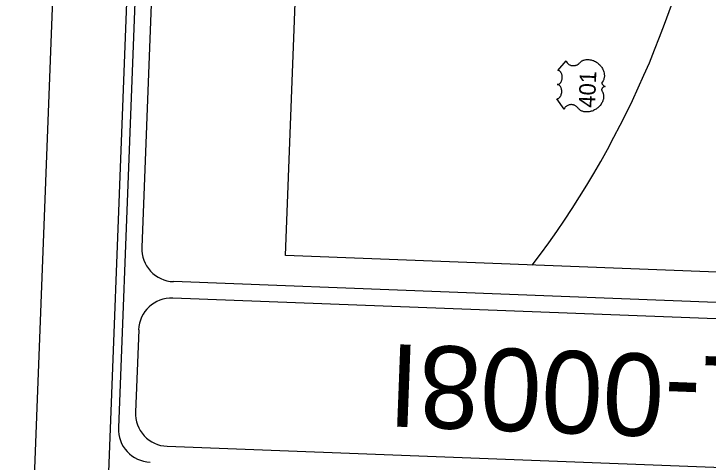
# Model space of a CAD drawing. Extents: x 2094564 to 2100382, y 679033 to 692366.
# Drawn here: x 2094564 to 2095618, y 683117 to 683797 of the extents above; entities that cross this region are included whole.
import ezdxf

# ---------------------------------------------------------------- set-up
doc = ezdxf.new("R2010")
doc.units = 0
for name, color, linetype in [('Default', 7, 'Continuous'), ('Pattern 17', 7, 'Continuous'), ('Prop Horizontal Alignment Direction Label', 7, 'Continuous'), ('Prop Horizontal Alignment Tick Label', 7, 'Continuous'), ('Prop Horizontal Alignment Tick Large', 7, 'Continuous')]:
    doc.layers.add(name, color=color, linetype=linetype)

msp = doc.modelspace()

# ---------------------------------------------------------------- linework, layer by layer
at = {"layer": 'Default'}
for p, q in [((2095431.1, 683727.5), (2095432.6, 683727.8)), ((2095432.6, 683727.8), (2095433.3, 683727.8)), ((2095433.3, 683727.8), (2095434.8, 683727.9)), ((2095434.8, 683727.9), (2095436.5, 683727.8)), ((2095436.5, 683727.8), (2095438.2, 683727.6)), ((2095389.4, 683711.4), (2095402, 683726)), ((2095402, 683726), (2095402.1, 683725.6)), ((2095402.1, 683725.6), (2095402.5, 683724.8)), ((2095402.5, 683724.8), (2095402.9, 683724.1)), ((2095402.9, 683724.1), (2095403.6, 683723)), ((2095403.6, 683723), (2095403.9, 683722.6)), ((2095403.9, 683722.6), (2095404.3, 683722.1)), ((2095404.3, 683722.1), (2095404.8, 683721.7)), ((2095404.8, 683721.7), (2095405.2, 683721.3)), ((2095405.2, 683721.3), (2095405.8, 683720.9)), ((2095405.8, 683720.9), (2095406.3, 683720.4)), ((2095406.3, 683720.4), (2095407, 683720)), ((2095407, 683720), (2095407.6, 683719.7)), ((2095407.6, 683719.7), (2095408.8, 683719.2)), ((2095408.8, 683719.2), (2095409.5, 683719)), ((2095409.5, 683719), (2095410.2, 683718.8)), ((2095410.2, 683718.8), (2095411.5, 683718.6)), ((2095411.5, 683718.6), (2095412.1, 683718.5)), ((2095412.1, 683718.5), (2095412.8, 683718.5)), ((2095412.8, 683718.5), (2095413.4, 683718.5)), ((2095413.4, 683718.5), (2095414.1, 683718.5)), ((2095414.1, 683718.5), (2095414.8, 683718.6)), ((2095414.8, 683718.6), (2095415.3, 683718.7)), ((2095415.3, 683718.7), (2095416.1, 683718.9)), ((2095416.1, 683718.9), (2095416.9, 683719.1)), ((2095416.9, 683719.1), (2095417.7, 683719.4)), ((2095417.7, 683719.4), (2095419.1, 683720)), ((2095419.1, 683720), (2095420.4, 683720.9)), ((2095420.4, 683720.9), (2095421.2, 683721.5)), ((2095421.2, 683721.5), (2095421.9, 683722.1)), ((2095421.9, 683722.1), (2095422.7, 683723)), ((2095422.7, 683723), (2095423.2, 683723.5)), ((2095423.2, 683723.5), (2095423.8, 683724)), ((2095423.8, 683724), (2095424.9, 683724.9)), ((2095424.9, 683724.9), (2095425.4, 683725.3)), ((2095425.4, 683725.3), (2095426, 683725.6)), ((2095426, 683725.6), (2095426.6, 683726)), ((2095426.6, 683726), (2095427.3, 683726.3)), ((2095427.3, 683726.3), (2095427.9, 683726.6)), ((2095427.9, 683726.6), (2095429.2, 683727)), ((2095429.2, 683727), (2095430.4, 683727.4)), ((2095430.4, 683727.4), (2095431.1, 683727.5)), ((2095438.2, 683727.6), (2095440.1, 683727.3)), ((2095440.1, 683727.3), (2095441.2, 683727)), ((2095441.2, 683727), (2095442.6, 683726.5)), ((2095442.6, 683726.5), (2095443.7, 683726.1)), ((2095443.7, 683726.1), (2095445.4, 683725.3)), ((2095445.4, 683725.3), (2095446.6, 683724.7)), ((2095446.6, 683724.7), (2095448, 683723.8)), ((2095448, 683723.8), (2095448.9, 683723.2)), ((2095448.9, 683723.2), (2095449.8, 683722.6)), ((2095449.8, 683722.6), (2095450.9, 683721.7)), ((2095450.9, 683721.7), (2095452, 683720.8)), ((2095452, 683720.8), (2095453.2, 683719.6)), ((2095453.2, 683719.6), (2095454, 683718.7)), ((2095454, 683718.7), (2095455, 683717.5)), ((2095455, 683717.5), (2095455.6, 683716.7)), ((2095389.9, 683711.3), (2095389.4, 683711.4)), ((2095390.4, 683711.2), (2095389.9, 683711.3)), ((2095391, 683711.1), (2095390.4, 683711.2)), ((2095391.6, 683710.8), (2095391, 683711.1)), ((2095392.1, 683710.5), (2095391.6, 683710.8)), ((2095392.6, 683710.1), (2095392.1, 683710.5)), ((2095393.3, 683709.5), (2095392.6, 683710.1)), ((2095393.9, 683708.8), (2095393.3, 683709.5)), ((2095394.3, 683708.2), (2095393.9, 683708.8)), ((2095394.8, 683707.5), (2095394.3, 683708.2)), ((2095395.2, 683706.5), (2095394.8, 683707.5)), ((2095455.6, 683716.7), (2095456.3, 683715.7)), ((2095456.3, 683715.7), (2095457.2, 683714.3)), ((2095457.2, 683714.3), (2095457.9, 683712.9)), ((2095457.9, 683712.9), (2095458.5, 683711.7)), ((2095458.5, 683711.7), (2095458.9, 683710.6)), ((2095458.9, 683710.6), (2095459.4, 683709.3)), ((2095459.4, 683709.3), (2095459.9, 683707)), ((2095459.9, 683707), (2095460, 683706.2)), ((2095395.5, 683705.8), (2095395.2, 683706.5)), ((2095395.3, 683695.5), (2095395.6, 683696.3)), ((2095395.8, 683705), (2095395.5, 683705.8)), ((2095395.6, 683696.3), (2095395.8, 683697.1)), ((2095396, 683704), (2095395.8, 683705)), ((2095395.8, 683697.1), (2095396, 683697.9)), ((2095396.1, 683703.3), (2095396, 683704)), ((2095396, 683697.9), (2095396.1, 683698.7)), ((2095396.2, 683702.5), (2095396.1, 683703.3)), ((2095396.1, 683698.7), (2095396.2, 683699.5)), ((2095396.3, 683701.7), (2095396.2, 683702.5)), ((2095396.2, 683700.1), (2095396.3, 683701)), ((2095396.2, 683699.5), (2095396.2, 683700.1)), ((2095396.3, 683701), (2095396.3, 683701.7)), ((2095458.7, 683696.6), (2095458.1, 683695.6)), ((2095459.1, 683697.7), (2095458.7, 683696.6)), ((2095459.5, 683698.9), (2095459.1, 683697.7)), ((2095459.8, 683700), (2095459.5, 683698.9)), ((2095460, 683701.1), (2095459.8, 683700)), ((2095460, 683706.2), (2095460.1, 683705.2)), ((2095460.2, 683702.3), (2095460, 683701.1)), ((2095460.1, 683705.2), (2095460.2, 683704.3)), ((2095460.2, 683704.3), (2095460.2, 683703.5)), ((2095460.2, 683703.5), (2095460.2, 683702.3)), ((2095389.5, 683689.7), (2095388.6, 683689.8)), ((2095388.6, 683689.8), (2095389.3, 683689.8)), ((2095389.3, 683689.8), (2095389.8, 683689.9)), ((2095389.9, 683689.6), (2095389.5, 683689.7)), ((2095389.8, 683689.9), (2095390.2, 683690)), ((2095390.8, 683689.3), (2095389.9, 683689.6)), ((2095390.2, 683690), (2095390.7, 683690.2)), ((2095390.7, 683690.2), (2095391.3, 683690.4)), ((2095391.2, 683689), (2095390.8, 683689.3)), ((2095391.6, 683688.7), (2095391.2, 683689)), ((2095391.3, 683690.4), (2095391.9, 683690.8)), ((2095392.4, 683688.1), (2095391.6, 683688.7)), ((2095391.9, 683690.8), (2095392.7, 683691.4)), ((2095393.1, 683687.2), (2095392.4, 683688.1)), ((2095392.7, 683691.4), (2095393.1, 683691.8)), ((2095393.1, 683691.8), (2095393.4, 683692.2)), ((2095393.5, 683686.7), (2095393.1, 683687.2)), ((2095393.4, 683692.2), (2095394.2, 683693.2)), ((2095393.9, 683685.9), (2095393.5, 683686.7)), ((2095394.4, 683685), (2095393.9, 683685.9)), ((2095394.2, 683693.2), (2095394.8, 683694.4)), ((2095394.8, 683694.4), (2095395.1, 683694.9)), ((2095395.1, 683694.9), (2095395.3, 683695.5)), ((2095456.5, 683693.2), (2095456.4, 683692.9)), ((2095456.4, 683692.9), (2095456.4, 683692.2)), ((2095456.4, 683692.2), (2095456.5, 683691.5)), ((2095456.8, 683693.7), (2095456.5, 683693.2)), ((2095456.5, 683691.5), (2095456.7, 683690.8)), ((2095456.7, 683690.8), (2095457, 683690.4)), ((2095458.1, 683695.6), (2095456.8, 683693.7)), ((2095457, 683690.4), (2095457.3, 683689.8)), ((2095457.3, 683689.8), (2095457.6, 683689.4)), ((2095457.6, 683689.4), (2095458.1, 683688.8)), ((2095458.6, 683685.9), (2095458, 683685.4)), ((2095458.1, 683688.8), (2095458.5, 683688.5)), ((2095458.5, 683688.5), (2095458.8, 683688.2)), ((2095459.1, 683686.3), (2095458.6, 683685.9)), ((2095458.8, 683688.2), (2095459.6, 683687.6)), ((2095459.6, 683686.6), (2095459.1, 683686.3)), ((2095459.6, 683687.6), (2095460, 683687.4)), ((2095460.3, 683686.8), (2095459.6, 683686.6)), ((2095460, 683687.4), (2095460.5, 683687.2)), ((2095461.2, 683687), (2095460.3, 683686.8)), ((2095460.5, 683687.2), (2095461.2, 683687)), ((2095394.7, 683684.2), (2095394.4, 683685)), ((2095394.4, 683673.7), (2095394.8, 683675)), ((2095394.9, 683683.3), (2095394.7, 683684.2)), ((2095394.8, 683675), (2095395.1, 683676.3)), ((2095395.1, 683682.5), (2095394.9, 683683.3)), ((2095395.4, 683680.8), (2095395.1, 683682.5)), ((2095395.1, 683676.3), (2095395.4, 683677.8)), ((2095395.4, 683679.2), (2095395.4, 683680.8)), ((2095395.4, 683677.8), (2095395.4, 683679.2)), ((2095456.2, 683682.9), (2095456, 683682.4)), ((2095456, 683682.4), (2095456, 683682)), ((2095456, 683682), (2095456, 683681.6)), ((2095456, 683681.6), (2095456.1, 683681.1)), ((2095456.1, 683681.1), (2095456.5, 683680.4)), ((2095456.4, 683683.4), (2095456.2, 683682.9)), ((2095456.6, 683683.8), (2095456.4, 683683.4)), ((2095456.5, 683680.4), (2095457, 683679.7)), ((2095457, 683684.4), (2095456.6, 683683.8)), ((2095457.5, 683685), (2095457, 683684.4)), ((2095457, 683679.7), (2095457.4, 683679)), ((2095457.4, 683679), (2095457.8, 683678.1)), ((2095458, 683685.4), (2095457.5, 683685)), ((2095457.8, 683678.1), (2095458, 683677.5)), ((2095458, 683677.5), (2095458.3, 683676.8)), ((2095458.3, 683676.8), (2095458.5, 683675.9)), ((2095458.5, 683675.9), (2095458.7, 683675)), ((2095387.8, 683668.3), (2095388.5, 683668.3)), ((2095399.3, 683652.7), (2095387.8, 683668.3)), ((2095388.5, 683668.3), (2095389.2, 683668.4)), ((2095389.2, 683668.4), (2095389.6, 683668.5)), ((2095389.6, 683668.5), (2095390.3, 683668.8)), ((2095390.3, 683668.8), (2095391.2, 683669.4)), ((2095391.2, 683669.4), (2095392.1, 683670.1)), ((2095392.1, 683670.1), (2095392.9, 683671)), ((2095392.9, 683671), (2095393.3, 683671.6)), ((2095393.3, 683671.6), (2095393.9, 683672.6)), ((2095393.9, 683672.6), (2095394.4, 683673.7)), ((2095457.7, 683664.9), (2095457.2, 683663.8)), ((2095458, 683665.9), (2095457.7, 683664.9)), ((2095458.3, 683666.9), (2095458, 683665.9)), ((2095458.6, 683667.8), (2095458.3, 683666.9)), ((2095458.8, 683668.9), (2095458.6, 683667.8)), ((2095458.7, 683675), (2095458.9, 683674)), ((2095458.9, 683669.8), (2095458.8, 683668.9)), ((2095458.9, 683674), (2095459, 683673.2)), ((2095459, 683670.6), (2095458.9, 683669.8)), ((2095459, 683673.2), (2095459, 683672.3)), ((2095459, 683672.3), (2095459, 683671.5)), ((2095459, 683671.5), (2095459, 683670.6)), ((2095399.8, 683653.9), (2095399.5, 683653.2)), ((2095400.3, 683654.7), (2095399.8, 683653.9)), ((2095400.8, 683655.3), (2095400.3, 683654.7)), ((2095401.3, 683655.9), (2095400.8, 683655.3)), ((2095402, 683656.5), (2095401.3, 683655.9)), ((2095402.8, 683657.2), (2095402, 683656.5)), ((2095403.7, 683657.8), (2095402.8, 683657.2)), ((2095404.7, 683658.3), (2095403.7, 683657.8)), ((2095405.5, 683658.6), (2095404.7, 683658.3)), ((2095406.5, 683659), (2095405.5, 683658.6)), ((2095407.4, 683659.2), (2095406.5, 683659)), ((2095408.4, 683659.3), (2095407.4, 683659.2)), ((2095409.4, 683659.4), (2095408.4, 683659.3)), ((2095410.3, 683659.4), (2095409.4, 683659.4)), ((2095411.4, 683659.3), (2095410.3, 683659.4)), ((2095412.2, 683659.2), (2095411.4, 683659.3)), ((2095413.2, 683658.9), (2095412.2, 683659.2)), ((2095413.9, 683658.7), (2095413.2, 683658.9)), ((2095414.9, 683658.4), (2095413.9, 683658.7)), ((2095415.5, 683658), (2095414.9, 683658.4)), ((2095416.4, 683657.6), (2095415.5, 683658)), ((2095417, 683657.2), (2095416.4, 683657.6)), ((2095417.6, 683656.7), (2095417, 683657.2)), ((2095418.3, 683656.2), (2095417.6, 683656.7)), ((2095418.8, 683655.7), (2095418.3, 683656.2)), ((2095419.6, 683654.8), (2095418.8, 683655.7)), ((2095420.2, 683654), (2095419.6, 683654.8)), ((2095420.9, 683653.2), (2095420.2, 683654)), ((2095449.3, 683653.9), (2095447.5, 683652.7)), ((2095450.3, 683654.7), (2095449.3, 683653.9)), ((2095451.8, 683656.1), (2095450.3, 683654.7)), ((2095452.7, 683657), (2095451.8, 683656.1)), ((2095453.8, 683658.3), (2095452.7, 683657)), ((2095455.1, 683660), (2095453.8, 683658.3)), ((2095456, 683661.5), (2095455.1, 683660)), ((2095456.6, 683662.4), (2095456, 683661.5)), ((2095457.2, 683663.8), (2095456.6, 683662.4)), ((2095399.5, 683653.2), (2095399.3, 683652.7)), ((2095421.7, 683652.4), (2095420.9, 683653.2)), ((2095422.5, 683651.8), (2095421.7, 683652.4)), ((2095423.3, 683651.1), (2095422.5, 683651.8)), ((2095424.1, 683650.6), (2095423.3, 683651.1)), ((2095425.1, 683650.1), (2095424.1, 683650.6)), ((2095426.2, 683649.6), (2095425.1, 683650.1)), ((2095427.1, 683649.3), (2095426.2, 683649.6)), ((2095427.8, 683649), (2095427.1, 683649.3)), ((2095428.9, 683648.7), (2095427.8, 683649)), ((2095430.2, 683648.5), (2095428.9, 683648.7)), ((2095431.3, 683648.3), (2095430.2, 683648.5)), ((2095432.4, 683648.3), (2095431.3, 683648.3)), ((2095433.6, 683648.2), (2095432.4, 683648.3)), ((2095434.9, 683648.3), (2095433.6, 683648.2)), ((2095436.2, 683648.4), (2095434.9, 683648.3)), ((2095437.1, 683648.5), (2095436.2, 683648.4)), ((2095438.4, 683648.8), (2095437.1, 683648.5)), ((2095439.1, 683648.9), (2095438.4, 683648.8)), ((2095440.3, 683649.3), (2095439.1, 683648.9)), ((2095441.5, 683649.7), (2095440.3, 683649.3)), ((2095442.9, 683650.2), (2095441.5, 683649.7)), ((2095443.8, 683650.6), (2095442.9, 683650.2)), ((2095445.3, 683651.3), (2095443.8, 683650.6)), ((2095446.3, 683651.9), (2095445.3, 683651.3)), ((2095447.5, 683652.7), (2095446.3, 683651.9))]:
    msp.add_line(p, q, dxfattribs=at)
at = {"layer": 'Pattern 17'}
msp.add_lwpolyline([(2094975.9, 683430.3), (2095048.9, 685332.8), (2096016.8, 685295.7), (2096009.9, 685115.7), (2096680.3, 685090), (2096614.3, 683367.4)], close=True, dxfattribs=at)
at = {"layer": 'Prop Horizontal Alignment Direction Label'}
for p, q in [((2098978.1, 683230.8), (2094806.2, 683390.8)), ((2099901.5, 683170.4), (2094805.2, 683365.8))]:
    msp.add_line(p, q, dxfattribs=at)
for points in [[(2095006.3, 690563.5), (2094722.6, 683168.8)], [(2095030.3, 690537.5), (2094758.2, 683442.8)], [(2094753.4, 683317.8), (2094748.6, 683192.9)], [(2094796.6, 683141.1), (2099892.9, 682945.6)]]:
    msp.add_lwpolyline(points, dxfattribs=at)
for centre, radius, start, end in [((2094220.3, 684274.7), 1419.7, 322.7766, 349.8037), ((2094807.9, 683440.8), 50, 177.8037, 267.8037), ((2094803.1, 683315.9), 50, 87.8037, 177.8037), ((2094798.3, 683191), 50, 177.8037, 267.8037), ((2094772.4, 683167), 50, 177.8037, 267.8037)]:
    msp.add_arc(centre, radius, start, end, dxfattribs=at)
at = {"layer": 'Prop Horizontal Alignment Tick Label'}
msp.add_lwpolyline([(2099950.1, 682147.8), (2100269.5, 690474.2), (2094997.8, 690676.3), (2094678.5, 682349.9)], close=True, dxfattribs=at)
at = {"layer": 'Prop Horizontal Alignment Tick Large'}
msp.add_lwpolyline([(2094886.5, 690703.1), (2094563.9, 682289.3), (2100059.8, 682078.5), (2100382.4, 690492.3)], close=True, dxfattribs=at)

# ---------------------------------------------------------------- texts
at = {"layer": 'Default'}
msp.add_text('401', height=24.9, rotation=87.8037, dxfattribs=at).set_placement((2095445.9, 683654.4))
at = {"layer": 'Prop Horizontal Alignment Direction Label'}
msp.add_text('HL-0008I', height=125, rotation=177.8037, dxfattribs=at).set_placement((2095822.1, 683269.9))

doc.saveas('drawing.dxf')
